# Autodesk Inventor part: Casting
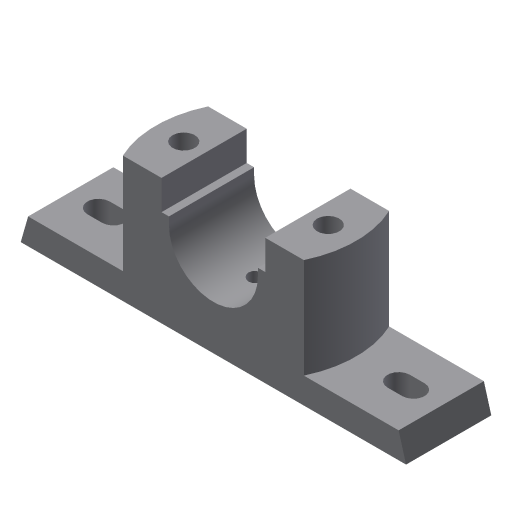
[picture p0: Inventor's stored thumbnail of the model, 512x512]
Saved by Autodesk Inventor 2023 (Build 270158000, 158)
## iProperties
Created: 2009-04
Part Number: Casting
Document SubType Name: Modeling
Designer: Sham
Density: 1 g/cm^3
Material: Generic
Appearance: Default
Author: Sham
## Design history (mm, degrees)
sketch "Sketch1"
  geometry: L1 (-104, 0)-(104, 0); L2 (-104, 0)-(-100, 14); L3 (-100, 14)-(100, 14); L4 (100, 14)-(104, 0); 1 further point
  constraints: 8 end point, 1 horizontal, 1 midpoint, 1 parallel, 1 other
  dimensions: "d0" = 208 distance of L1.start L1.end; "d1" = 104 distance of L1.end point (0, 0); "d2" = 4 horizontal distance of L1.start L2.end; "d3" = 4 horizontal distance of L1.end L3.end; "d10" = 14 distance between parallel lines of L1 L3
extrude "Extrusion1" new body sketch "Sketch1" stored distance "d4" = 46; taper "d5" = 0 deg
sketch "Sketch2"
  geometry: L1 (51.143, 46)-(148.857, 46); L2 (148.857, 0)-(51.143, 0); A1 r 54 centre (100, 23) between (51.143, 46) and (51.143, 0); A2 r 54 centre (100, 23) between (148.857, 0) and (148.857, 46)
  constraints: 4 end point, 4 point on circle, 2 centre point, 1 parallel
extrude "Extrusion2" join sketch "Sketch2" distance "d8" = 54; taper "d9" = 0 deg
sketch "Sketch3"
  geometry: L1 (-28, 68)-(-28, 52); L2 (-28, 52)-(-24, 52); L3 (28, 68)-(28, 52); L4 (28, 52)-(24, 52); L5 (-28, 68)-(28, 68); L6 (-100, 14)-(-48.857, 14) reference; L7 (0, 48)-(0, 19); L8 (48.857, 14)-(100, 14) reference; L9 (48.857, 68)-(-48.857, 68) reference; L10 (-24, 48)-(-24, 52); L11 (24, 48)-(24, 52); A1 r 24 centre (0, 48) between (-24, 48) and (24, 48); 1 further point
  constraints: 16 end point, 5 perpendicular, 2 point on circle, 2 symmetric about line, 1 centre point, 1 tangent, 1 vertical alignment, 1 other
  dimensions: "d11" = 16 distance of L1.start L1.end; "d16" = 24 radius of A1; "d17" = 16 distance of L3.start L3.end; "d52" = 56 distance between parallel lines of L1 L3; "d54" = 54 distance between parallel lines of L8 L9 (derived)
extrude "Extrusion3" cut sketch "Sketch3" distance "d18" = 54; taper "d19" = 0 deg
sketch "Sketch4"
  geometry: L1 (-23, 29)-(-15, 29); L2 (-15, 17)-(-23, 17); L3 (-185, 29)-(-177, 29); L4 (-177, 17)-(-185, 17); A1 r 6 centre (-15, 23) between (-15, 17) and (-15, 29); A2 r 6 centre (-23, 23) between (-23, 29) and (-23, 17); A3 r 6 centre (-177, 23) between (-177, 17) and (-177, 29); A4 r 6 centre (-185, 23) between (-185, 29) and (-185, 17)
  constraints: 8 end point, 8 point on circle, 8 tangent, 4 centre point, 3 parallel
  dimensions: "d20" = 8 distance of A1.centre A2.centre; "d21" = 6 radius of A1; "d24" = 6 radius of A3; "d25" = 8 distance of A4.centre A3.centre
extrude "Extrusion4" cut sketch "Sketch4" distance "d28" = 54; taper "d29" = 0 deg
sketch "Sketch5"
  geometry: L1 (208, 0)-(0, 0) reference; L2 (52, -10)-(78, -10); L3 (78, -10)-(78, -36); L4 (78, -36)-(52, -36); L5 (52, -36)-(52, -10); L6 (130, -10)-(156, -10); L7 (156, -10)-(156, -36); L8 (156, -36)-(130, -36); L9 (130, -36)-(130, -10); L10 (0, -46)-(208, -46) reference; L11 (104, -23)-(104, -46)
  constraints: 18 end point, 5 perpendicular, 4 parallel, 2 horizontal, 1 midpoint
  dimensions: "d30" = 26 distance of L2.start L2.end; "d31" = 10 distance between parallel lines of L2 L1; "d32" = 10 distance between parallel lines of L1 L6; "d65" = 26 distance between parallel lines of L3 L11; "d66" = 26 distance between parallel lines of L9 L11
extrude "Extrusion5" cut sketch "Sketch5" distance "d34" = 10; taper "d35" = 0 deg
sketch "Sketch6"
  geometry: L1 (148.857, 0)-(128, 0) reference; L2 (72, 0)-(51.143, 0) reference; L3 (0, 46)-(0, 0) reference; L4 (200, 46)-(200, 0) reference; C1 r 6 at (61, 23); C2 r 6 at (139, 23); 1 further point
  constraints: 2 centre point, 1 equal radius
  dimensions: "d36" = 12 diameter of C1; "d37" = 78 distance of C2.centre C1.centre; "d39" = 39 distance of C2.centre point (100, 23); "d58" = 39 distance of C1.centre point (100, 23); "d59" = 23 distance from line of L1 C2.centre; "d60" = 23 distance from line of L2 C1.centre; "d61" = 61 distance from line of L3 C1.centre; "d62" = 61 distance from line of L4 C2.centre (derived)
extrude "Extrusion6" cut sketch "Sketch6" extent not by distance; stored distance "d40" = 10; taper "d41" = 0 deg
workplane "Work Plane1"
sketch "Sketch7"
  geometry: L1 (-4, 46)-(204, 46) reference; L2 (-4, 0)-(-4, 46) reference; 1 further point
  dimensions: "d43" = 23 distance from line of L1 point (100, 23); "d44" = 104 distance from line of point (100, 23) L2
hole "Hole1" sketch "Sketch7" at (100, 23) diameter "d45" = 8; stored, may be unused: countersink angle "d49" = 90 deg, drill point angle "d51" = 118 deg; dims "d46" = 6, "d47" = 8, "d48" = 16, "d50" = 8
body "Solid1"
other parameters: "d6" = 108, "d42" = -52
